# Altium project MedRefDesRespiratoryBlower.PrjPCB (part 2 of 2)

## Sheet Power Tree.SchDoc
size 431 x 279 mm; Date: Not shown in title block; ApprovedBy: Not shown in title block; CheckedBy: Not shown in title block; Author: Not shown in title block; CompanyName: Not shown in title block; Engineer: Not shown in title block; Organization: Not shown in title block; Address1: Not shown in title block; Address2: Not shown in title block; Address3: Not shown in title block; Address4: Not shown in title block; DocumentNumber: 5; Revision: Use project parameter SCH_Rev; SheetNumber: 5; SheetTotal: 6; PageSetup: Record=PageOptions¦CenterHorizontal=True¦CenterVertical=True¦PrintScale=1.00¦XCorrection=1.00¦YCorrection=1.00¦PrintKind=0¦BorderSize=5000000¦LeftOffset=0¦BottomOffset=0¦Orientation=2¦PaperLength=1000¦PaperWidth=1000¦Scale=100¦PaperSource=15¦PrintQuality=600¦MediaType=1¦DitherType=10¦PaperKind=Letter¦PrintScaleMode=1
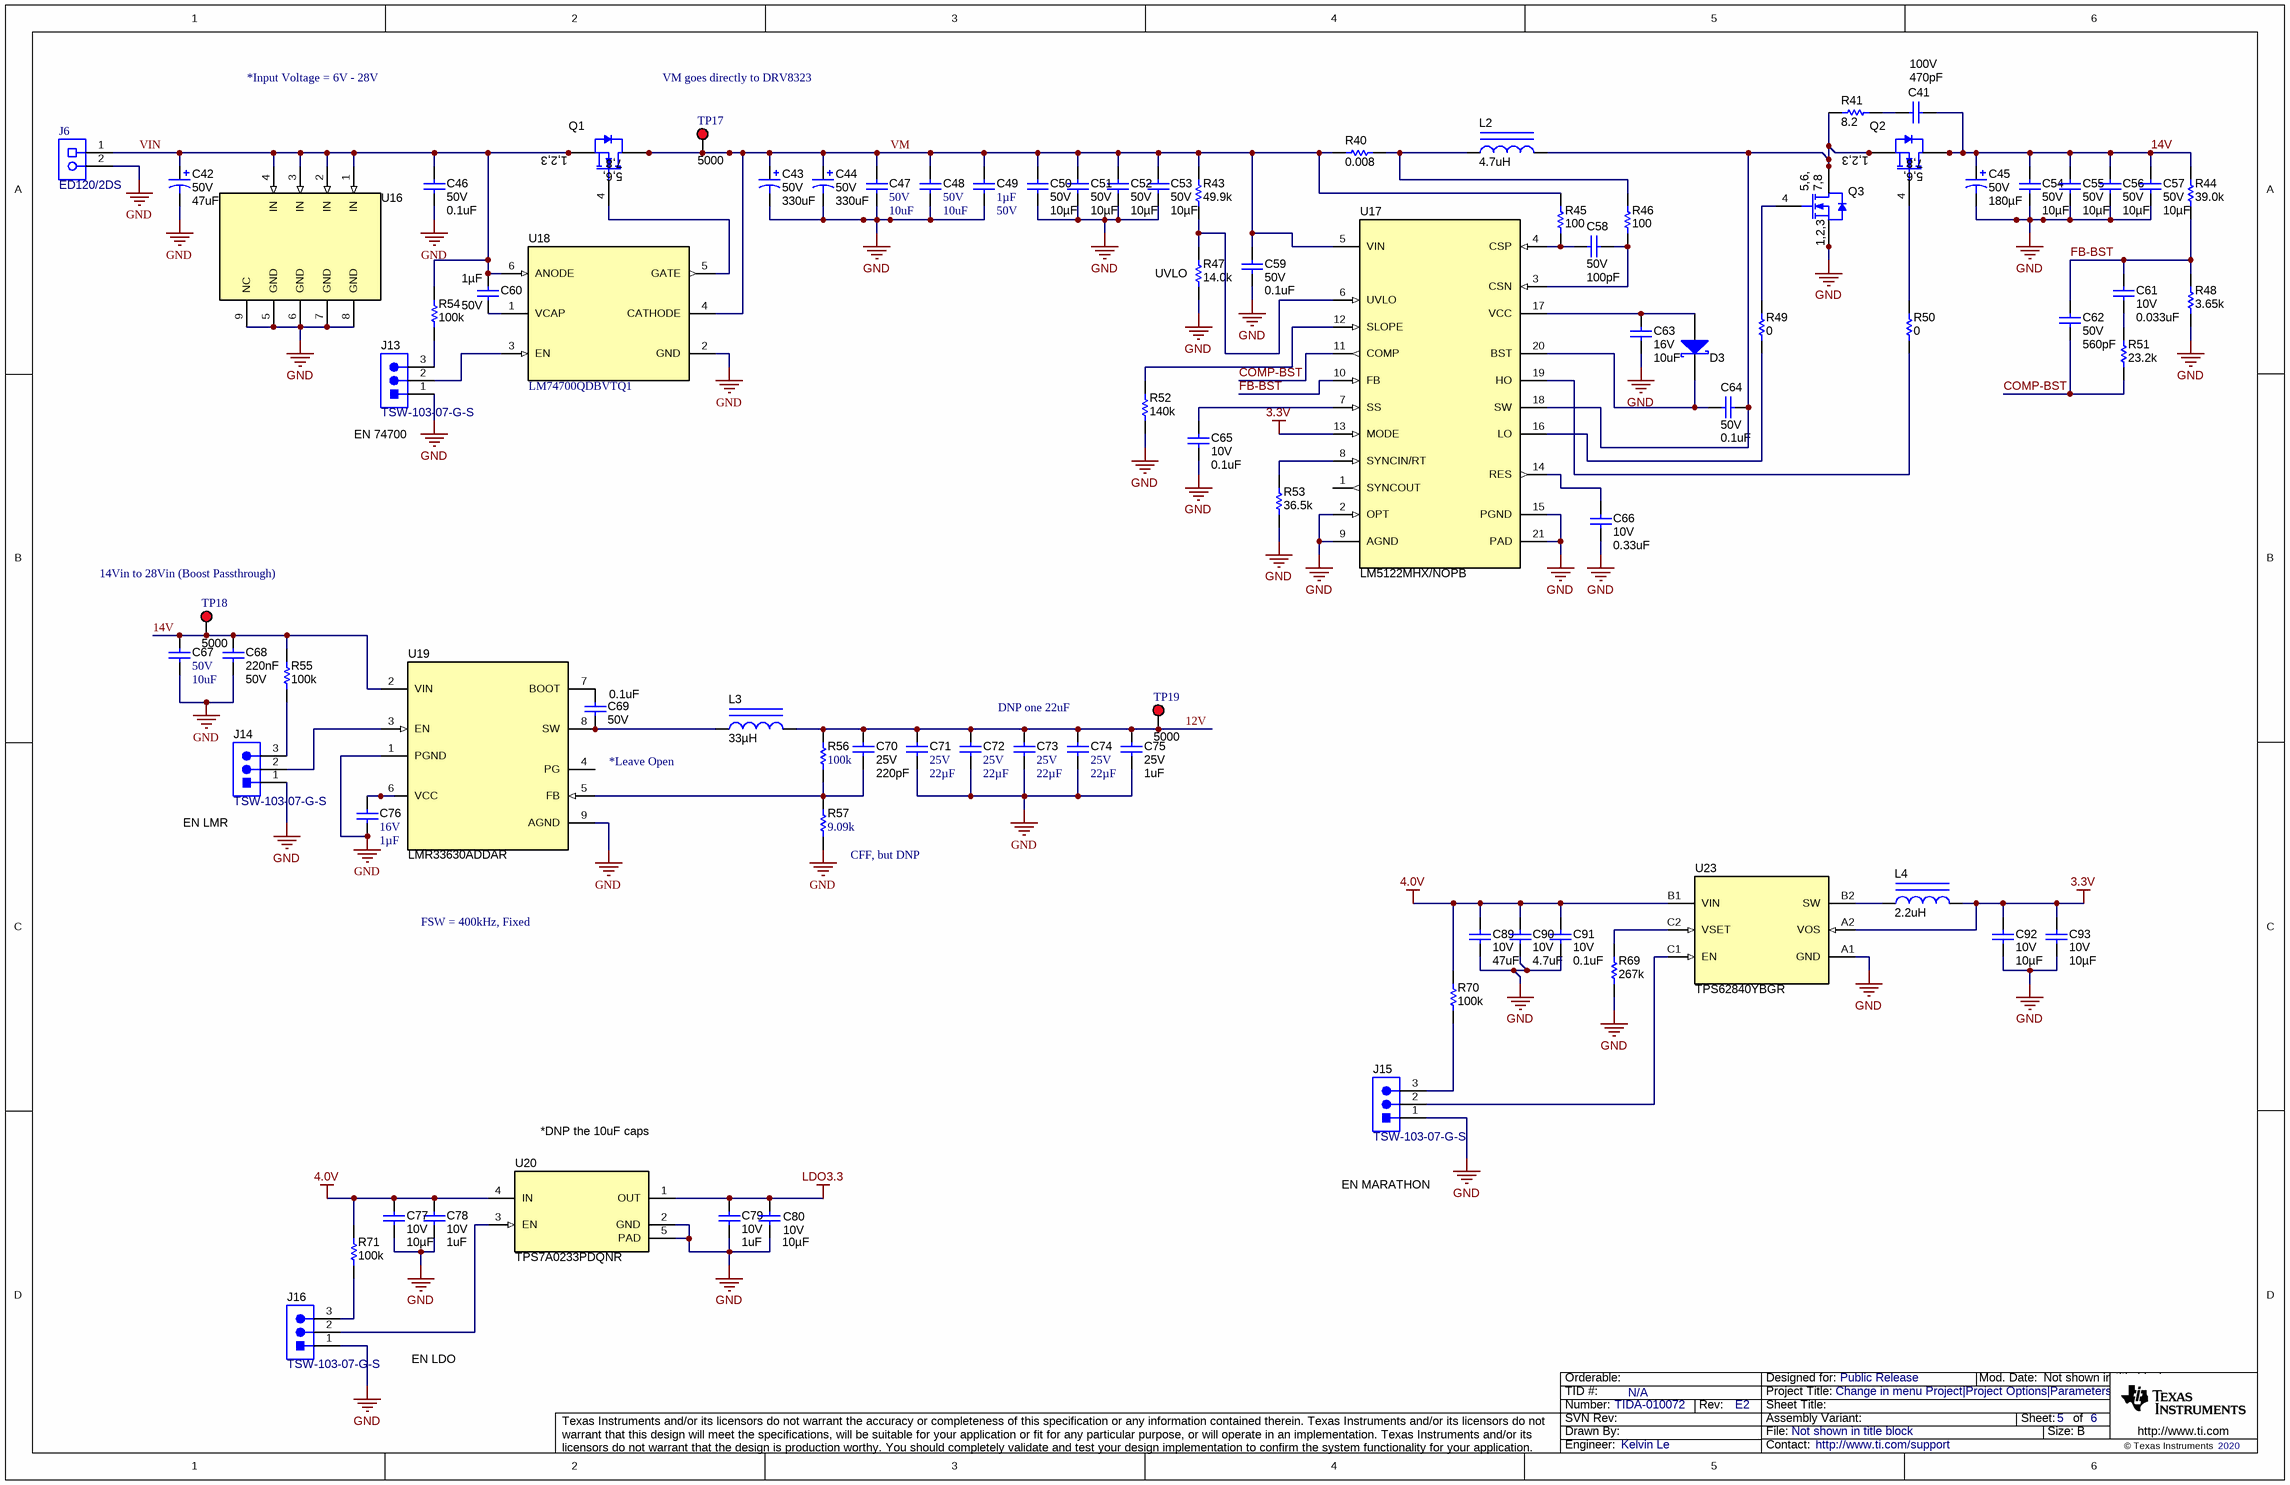
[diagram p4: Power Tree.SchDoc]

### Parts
C41  Cap_F: 470pF  VDC_V: 100V  [0603]  (hidden comment: GRM188R72A471KA01D)
C42  VDC_V: 50V  ValueDisplayed: 47uF  [CAPSMT_62_F80]  (hidden comment: EMZA500ADA470MF80G)
C43  VDC_V: 50V  ValueDisplayed: 330uF  [CAPSMT_62_KE0]  (hidden comment: EMVA500ATR331MKE0S)
C44  VDC_V: 50V  ValueDisplayed: 330uF  [CAPSMT_62_KE0]  (hidden comment: EMVA500ATR331MKE0S)
C45  VDC_V: 50V  ValueDisplayed: 180µF  [SM_RADIAL_F]  (hidden comment: EEE-FK1H181SP)
C46  VDC_V: 50V  ValueDisplayed: 0.1uF  [0402]  (hidden comment: C1005X7R1H104K050BB)
C47  VDC_V: 50V  ValueDisplayed: 10uF  [1206_180]  (hidden comment: CL31B106KBHNNNE)
C48  VDC_V: 50V  ValueDisplayed: 10uF  [1206_180]  (hidden comment: CL31B106KBHNNNE)
C49  Cap_F: 1µF  VDC_V: 50V  [0603]  (hidden comment: UMK107AB7105KA-T)
C50  VDC_V: 50V  ValueDisplayed: 10µF  [1206_190]  (hidden comment: UMK316BBJ106KL-T)
C51  VDC_V: 50V  ValueDisplayed: 10µF  [1206_190]  (hidden comment: UMK316BBJ106KL-T)
C52  VDC_V: 50V  ValueDisplayed: 10µF  [1206_190]  (hidden comment: UMK316BBJ106KL-T)
C53  VDC_V: 50V  ValueDisplayed: 10µF  [1206_190]  (hidden comment: UMK316BBJ106KL-T)
C54  VDC_V: 50V  ValueDisplayed: 10µF  [1206_190]  (hidden comment: UMK316BBJ106KL-T)
C55  VDC_V: 50V  ValueDisplayed: 10µF  [1206_190]  (hidden comment: UMK316BBJ106KL-T)
C56  VDC_V: 50V  ValueDisplayed: 10µF  [1206_190]  (hidden comment: UMK316BBJ106KL-T)
C57  VDC_V: 50V  ValueDisplayed: 10µF  [1206_190]  (hidden comment: UMK316BBJ106KL-T)
C58  VDC_V: 50V  ValueDisplayed: 100pF  [0402]  (hidden comment: 885012205055)
C59  VDC_V: 50V  ValueDisplayed: 0.1uF  [0402]  (hidden comment: GRM155R61H104ME14D)
C60  Cap_F: 1µF  VDC_V: 50V  [0603]  (hidden comment: UMK107AB7105KA-T)
C61  VDC_V: 10V  ValueDisplayed: 0.033uF  [0402]  (hidden comment: GRM155R61A333KA01D)
C62  VDC_V: 50V  ValueDisplayed: 560pF  [0402]  (hidden comment: GRM155R71H561KA01D)
C63  VDC_V: 16V  ValueDisplayed: 10uF  [0603]  (hidden comment: EMK107BBJ106MA-T)
C64  VDC_V: 50V  ValueDisplayed: 0.1uF  [0402]  (hidden comment: C1005X5R1H104K050BB)
C65  VDC_V: 10V  ValueDisplayed: 0.1uF  [0402]  (hidden comment: C1005X5R1A104K050BA)
C66  VDC_V: 10V  ValueDisplayed: 0.33uF  [0402]  (hidden comment: C1005X5R1A334K050BB)
C67  VDC_V: 50V  ValueDisplayed: 10uF  [1206_180]  (hidden comment: CL31B106KBHNNNE)
C68  Cap_F: 220nF  VDC_V: 50V  [0603]  (hidden comment: C1608X7R1H224K080AB)
C69  VDC_V: 50V  ValueDisplayed: 0.1uF  [0402]  (hidden comment: C1005X7R1H104K050BB)
C70  VDC_V: 25V  ValueDisplayed: 220pF  [0201]  (hidden comment: GRM033R71E221KA01D)
C71  VDC_V: 25V  ValueDisplayed: 22µF  [1210_270]  (hidden comment: GRT32ER61E226KE13L)
C72  VDC_V: 25V  ValueDisplayed: 22µF  [1210_270]  (hidden comment: GRT32ER61E226KE13L)
C73  VDC_V: 25V  ValueDisplayed: 22µF  [1210_270]  (hidden comment: GRT32ER61E226KE13L)
C74  VDC_V: 25V  ValueDisplayed: 22µF  [1210_270]  (hidden comment: GRT32ER61E226KE13L)
C75  VDC_V: 25V  ValueDisplayed: 1uF  [0402]  (hidden comment: GRM155R61E105KA12D)
C76  VDC_V: 16V  ValueDisplayed: 1µF  [0603]  (hidden comment: CC0603MRX5R7BB105)
C77  VDC_V: 10V  ValueDisplayed: 10µF  [0402_070]  (hidden comment: CC0402MRX5R6BB106)
C78  VDC_V: 10V  ValueDisplayed: 1uF  [0402]  (hidden comment: GRM155R61A105KE15D)
C79  VDC_V: 10V  ValueDisplayed: 1uF  [0402]  (hidden comment: GRM155R61A105KE15D)
C80  VDC_V: 10V  ValueDisplayed: 10µF  [0402_070]  (hidden comment: CC0402MRX5R6BB106)
C89  VDC_V: 10V  ValueDisplayed: 47uF  [0805_HV]  (hidden comment: C2012X5R1A476M125AC)
C90  VDC_V: 10V  ValueDisplayed: 4.7uF  [0402_065]  (hidden comment: C1005X5R1A475K050BC)
C91  VDC_V: 10V  ValueDisplayed: 0.1uF  [0402]  (hidden comment: 885012105010)
C92  VDC_V: 10V  ValueDisplayed: 10µF  [0402_070]  (hidden comment: CC0402MRX5R6BB106)
C93  VDC_V: 10V  ValueDisplayed: 10µF  [0402_070]  (hidden comment: CC0402MRX5R6BB106)
D3  MBR1H100SFT3G  [SOD-123FL]  (value not drawn)
J6  ED120/2DS  [On-Shore_ED120_2DS]
J13  TSW-103-07-G-S  [TSW-103-07-G-S]
J14  TSW-103-07-G-S  [TSW-103-07-G-S]
J15  TSW-103-07-G-S  [TSW-103-07-G-S]
J16  TSW-103-07-G-S  [TSW-103-07-G-S]
L2  ValueDisplayed: 4.7uH  [XAL6060]  (hidden comment: XAL6060-472MEB)
L3  ValueDisplayed: 33µH  [XAL6060]  (hidden comment: XAL6060-333MEB)
L4  ValueDisplayed: 2.2uH  [XFL3012]  (hidden comment: XFL3012-222MEB)
Q1  CSD18532Q5B  [DNK0008A]  (value not drawn)
Q2  CSD18543Q3A  [DNH0008A]  (value not drawn)
Q3  CSD18543Q3A  [DNH0008A]  (value not drawn)
R40  ValueDisplayed: 0.008  [2512]  (hidden comment: PMR100HZPFU8L00)
R41  ValueDisplayed: 8.2  [1210]  (hidden comment: RC1210JR-078R2L)
R43  ValueDisplayed: 49.9k  [0402]  (hidden comment: MCR01MZPF4992)
R44  ValueDisplayed: 39.0k  [0402]  (hidden comment: ERJ2RKF3902X)
R45  ValueDisplayed: 100  [0402]  (hidden comment: CRCW0402100RFKED)
R46  ValueDisplayed: 100  [0402]  (hidden comment: CRCW0402100RFKED)
R47  ValueDisplayed: 14.0k  [0402]  (hidden comment: RC0402FR-0714KL)
R48  ValueDisplayed: 3.65k  [0402]  (hidden comment: CRCW04023K65FKED)
R49  ValueDisplayed: 0  [0402]  (hidden comment: CRCW04020000Z0EDHP)
R50  ValueDisplayed: 0  [0402]  (hidden comment: CRCW04020000Z0EDHP)
R51  ValueDisplayed: 23.2k  [0402]  (hidden comment: CRCW040223K2FKED)
R52  ValueDisplayed: 140k  [0402]  (hidden comment: CRCW0402140KFKED)
R53  ValueDisplayed: 36.5k  [0402]  (hidden comment: CRCW040236K5FKED)
R54  ValueDisplayed: 100k  [0402]  (hidden comment: CRCW0402100KJNED)
R55  ValueDisplayed: 100k  [0402]  (hidden comment: CRCW0402100KJNED)
R56  ValueDisplayed: 100k  [0402]  (hidden comment: RMCF0402FT100K)
R57  ValueDisplayed: 9.09k  [0402]  (hidden comment: CRCW04029K09FKED)
R69  ValueDisplayed: 267k  [0402]  (hidden comment: CRCW0402267KFKED)
R70  ValueDisplayed: 100k  [0402]  (hidden comment: CRCW0402100KJNED)
R71  ValueDisplayed: 100k  [0402]  (hidden comment: CRCW0402100KJNED)
TP17  5000  [Keystone5000]
TP18  5000  [Keystone5000]
TP19  5000  [Keystone5000]
U16  TVS3301DRBR  [DRB0008A]  (value not drawn)
U17  LM5122MHX/NOPB  [PWP0020A_N]
U18  LM74700QDBVTQ1  [DBV0006A_N]
U19  LMR33630ADDAR  [DDA0008J]
U20  TPS7A0233PDQNR  [DQN0004A]
U23  TPS62840YBGR  [YBG0006AJAN]

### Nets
3.3V: C92.1 C93.1 L4.2 U17.13(MODE) U23.A2(VOS)
4.0V: C77.1 C78.1 C89.1 C90.1 C91.1 R70.2 R71.2 U20.4(IN) U23.B1(VIN)
GND: C42.2(-) C43.2(-) C44.2(-) C45.2(-) C46.2 C47.2 C48.2 C49.2 C50.2 C51.2 C52.2 C53.2 C54.2 C55.2 C56.2 C57.2 C59.2 C63.2 C65.2 C66.2 C67.2 C68.2 C71.2 C72.2 C73.2 C74.2 C75.2 C76.2 C77.2 C78.2 C79.2 C80.2 C89.2 C90.2 C91.2 C92.2 C93.2 J6.2 J13.1 J14.1 J15.1 J16.1 Q3.1(S) Q3.2(S) Q3.3(S) R47.1 R48.1 R52.1 R53.1 R57.1 R69.1 U16.5(GND) U16.6(GND) U16.7(GND) U16.8(GND) U16.9(NC) U17.2(OPT) U17.9(AGND) U17.15(PGND) U17.21(PAD) U18.2(GND) U19.1(PGND) U19.9(AGND) U20.2(GND) U20.5(PAD) U23.A1(GND)
LDO3.3: C79.1 C80.1 U20.1(OUT)
VM: C43.1(+) C44.1(+) C47.1 C48.1 C49.1 C50.1 C51.1 C52.1 C53.1 C59.1 Q1.5(D) Q1.6(D) Q1.7(D) Q1.8(D) Q1.9(D) R40.1 R43.2 R45.2 TP17.1 U17.5(VIN) U18.4(CATHODE)  [project net VDRAIN]
12V: C70.1 C71.1 C72.1 C73.1 C74.1 C75.1 L3.2 R56.2 TP19.1
14V: C41.1 C45.1(+) C54.1 C55.1 C56.1 C57.1 C67.1 C68.1 Q2.5(D) Q2.6(D) Q2.7(D) Q2.8(D) Q2.9(D) R44.2 R55.2 TP18.1 U19.2(VIN)
COMP-BST: C62.2 R51.1 U17.11(COMP)
FB-BST: C61.1 C62.1 R44.1 R48.2 U17.10(FB)
VIN: C42.1(+) C46.1 C60.1 J6.1 Q1.1(S) Q1.2(S) Q1.3(S) R54.2 U16.1(IN) U16.2(IN) U16.3(IN) U16.4(IN) U18.6(ANODE)
NetC41_2: C41.2 R41.2
NetC58_1: C58.1 R46.1 U17.3(CSN)
NetC58_2: C58.2 R45.1 U17.4(CSP)
NetC60_2: C60.2 U18.1(VCAP)
NetC61_2: C61.2 R51.2
NetC63_1: C63.1 D3.2(A) U17.17(VCC)
NetC64_1: C64.1 L2.2 Q2.1(S) Q2.2(S) Q2.3(S) Q3.5(D) Q3.6(D) Q3.7(D) Q3.8(D) Q3.9(D) R41.1 U17.18(SW)
NetC64_2: C64.2 D3.1(K) U17.20(BST)
NetC65_1: C65.1 U17.7(SS)
NetC66_1: C66.1 U17.14(RES)
NetC69_1: C69.1 U19.7(BOOT)
NetC69_2: C69.2 L3.1 U19.8(SW)
NetC70_2: C70.2 R56.1 R57.2 U19.5(FB)
NetC76_1: C76.1 U19.6(VCC)
NetJ13_2: J13.2 U18.3(EN)
NetJ13_3: J13.3 R54.1
NetJ14_2: J14.2 U19.3(EN)
NetJ14_3: J14.3 R55.1
NetJ15_2: J15.2 U23.C1(EN)
NetJ15_3: J15.3 R70.1
NetJ16_2: J16.2 U20.3(EN)
NetJ16_3: J16.3 R71.1
NetL2_1: L2.1 R40.2 R46.2
NetL4_1: L4.1 U23.B2(SW)
NetQ1_4: Q1.4(G) U18.5(GATE)
NetQ2_4: Q2.4(G) R50.2
NetQ3_4: Q3.4(G) R49.2
NetR43_1: R43.1 R47.2 U17.6(UVLO)
NetR49_1: R49.1 U17.16(LO)
NetR50_1: R50.1 U17.19(HO)
NetR52_2: R52.2 U17.12(SLOPE)
NetR53_2: R53.2 U17.8(SYNCIN/RT)
NetR69_2: R69.2 U23.C2(VSET)

Not connected (* = marked no-connect by the designer): U17 1(SYNCOUT); U19 4(PG)

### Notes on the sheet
- *Input Voltage = 6V - 28V
- VM goes directly to DRV8323
- (near R47) UVLO
- (near J13) EN 74700
- (near TP18) 14Vin to 28Vin (Boost Passthrough)
- *Leave Open
- DNP one 22uF
- (near J14) EN LMR
- (near R57) CFF, but DNP
- FSW = 400kHz, Fixed
- *DNP the 10uF caps
- EN MARATHON
- EN LDO

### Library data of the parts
C41 = CMP-0007482-3: CAP, CERM, 470 pF, 100 V, +/- 10%, X7R, 0603; Manufacturer: MuRata; TaMin_C: -55°C; Polarized: N; SizeAreaWB_mm2: 4.68; Value1: Unknown; U/M: EA; Value: 470pF; TaMax_C: 125°C; SizeZ_mm: 1; SizeX_mm: 1.6; SizeY_mm: 0.8; SizeArea_mm2: 1.28; AEC Category: Q200
C42 = CMP-0011388-2: CAP, AL, 47 uF, 50 V, +/- 20%, 0.68 ohm, SMD; Manufacturer: Chemi-Con; TaMin_C: -55°C; ESR_ohm: 0.68; Polarized: Y; SizeAreaWB_mm2: 73.96; U/M: EA; Value: 47uF; TaMax_C: 105°C; SizeZ_mm: 7.7; SizeX_mm: 6.6; Cap_Case: F80; SizeArea_mm2: 43.56; CompType: Capacitor; Cap_F: 47µF; IRMS_A: 195mA; AEC Category: Q200
C43 C44 = CMP-0011243-1: CAP, AL, 330 uF, 50 V, +/- 20%, SMD; Manufacturer: Chemi-Con; TaMin_C: -40°C; Polarized: Y; SizeAreaWB_mm2: 225; Value1: Unknown; U/M: EA; Value: 330uF; TaMax_C: 85°C; SizeZ_mm: 13.5; SizeX_mm: 13; Cap_Case: KE0; SizeArea_mm2: 169; CompType: Capacitor; Cap_F: 330µF; IRMS_A: 600mA; AEC Category: Q200
C45 = CMP-0078149-1: CAP, AL, 180 µF, 50 V, +/- 20%, 0.34 ohm, AEC-Q200 Grade 2, SMD; Manufacturer: Panasonic; IRMS_A: 350mA; SizeAreaWB_mm2: 123.6; SizeArea_mm2: 83; AEC Qualified: Y; AEC Category: Q200; Value: 180uF; TaMax_C: 105°C; SizeZ_mm: 10.2; AEC Grade: 2; TaMin_C: -55°C; SizeY_mm: 8.3; U/M: EA; CompType: Capacitor; SizeX_mm: 10; ESR_ohm: 0.34; Cap_Case: 8X10.2mm
C46 C69 = CMP-0006297-2: CAP, CERM, 0.1 uF, 50 V, +/- 10%, X7R, 0402; Manufacturer: TDK; TaMin_C: -55°C; ESR_ohm: 0.039064; Polarized: N; SizeAreaWB_mm2: 3; Value1: 0.039064 ohm; U/M: EA; Value: 0.1uF; TaMax_C: 125°C; SizeZ_mm: 0.6; SizeX_mm: 1; SizeY_mm: 0.5; Cap_F: 100nF; IRMS_A: 814.669mA; AEC Category: Q200
C47 C48 C67 = CMP-0008802-2: CAP, CERM, 10 uF, 50 V, +/- 10%, X7R, 1206; Manufacturer: Samsung; TaMin_C: -55°C; Polarized: N; SizeAreaWB_mm2: 10.92; Value1: Unknown; U/M: EA; Value: 10uF; TaMax_C: 125°C; SizeZ_mm: 1.8; SizeX_mm: 3.2; SizeY_mm: 1.6; Cap_Case: 1206; SizeArea_mm2: 5.12; Cap_F: 10µF; AEC Category: Q200
C49 C60 = CMP-0007508-5: CAP, CERM, 1 uF, 50 V, +/- 10%, X7R, 0603; Manufacturer: Taiyo Yuden; TaMin_C: -55°C; Polarized: N; SizeAreaWB_mm2: 4.68; Value1: Unknown; U/M: EA; Value: 1uF; TaMax_C: 125°C; SizeZ_mm: 1; SizeX_mm: 1.6; SizeY_mm: 0.8; SizeArea_mm2: 1.28; AEC Category: Q200
C50-C57 = CMP-0086153-1: CAP, CERM, 10 µF, 50 V,+/- 10%, X5R, 1206; Manufacturer: Taiyo Yuden; Polarized: N; SizeX_mm: 3.2; TaMax_C: 85°C; SizeY_mm: 1.6; AEC Category: Q200; SizeArea_mm2: 5.12; Cap_Case: 1206; SizeAreaWB_mm2: 10.92; TaMin_C: -55°C; SizeZ_mm: 1.9; U/M: EA; Value: 10uF
C58 = CMP-0006230-2: CAP, CERM, 100 pF, 50 V, +/- 10%, X7R, 0402; Manufacturer: Wurth Elektronik; TaMin_C: -55°C; Polarized: N; SizeAreaWB_mm2: 3; Value1: Unknown; U/M: EA; Value: 100pF; TaMax_C: 125°C; SizeZ_mm: 0.6; SizeX_mm: 1; SizeY_mm: 0.5; AEC Category: Q200
C59 = CMP-0006614-2: CAP, CERM, 0.1 uF, 50 V, +/- 20%, X5R, 0402; Manufacturer: MuRata; TaMin_C: -55°C; Polarized: N; SizeAreaWB_mm2: 3; Value1: Unknown; U/M: EA; Value: 0.1uF; TaMax_C: 85°C; SizeZ_mm: 0.6; SizeX_mm: 1; SizeY_mm: 0.5; Cap_F: 100nF; AEC Category: Q200
C61 = CMP-0006574-2: CAP, CERM, 0.033 uF, 10 V, +/- 10%, X5R, 0402; Manufacturer: MuRata; TaMin_C: -55°C; Polarized: N; SizeAreaWB_mm2: 3; Value1: Unknown; U/M: EA; TaMax_C: 85°C; SizeZ_mm: 0.6; SizeX_mm: 1; SizeY_mm: 0.5; Cap_F: 33nF; AEC Category: Q200
C62 = CMP-0006693-2: CAP, CERM, 560 pF, 50 V, +/- 10%, X7R, 0402; Manufacturer: MuRata; TaMin_C: -55°C; Polarized: N; SizeAreaWB_mm2: 3; Value1: Unknown; U/M: EA; Value: 560pF; TaMax_C: 125°C; SizeZ_mm: 0.6; SizeX_mm: 1; SizeY_mm: 0.5; AEC Category: Q200
C63 = CMP-0007122-5: CAP, CERM, 10 uF, 16 V, +/- 20%, X5R, 0603; Manufacturer: Taiyo Yuden; TaMin_C: -55°C; Polarized: N; SizeAreaWB_mm2: 4.68; Value1: Unknown; U/M: EA; Value: 10uF; TaMax_C: 85°C; SizeZ_mm: 1; SizeX_mm: 1.6; SizeY_mm: 0.8; SizeArea_mm2: 1.28; Cap_F: 10µF; AEC Category: Q200
C64 = CMP-0006279-2: CAP, CERM, 0.1 uF, 50 V, +/- 10%, X5R, 0402; Manufacturer: TDK; TaMin_C: -55°C; ESR_ohm: 0.039064; Polarized: N; SizeAreaWB_mm2: 3; Value1: 0.039064 ohm; U/M: EA; Value: 0.1uF; TaMax_C: 85°C; SizeZ_mm: 0.6; SizeX_mm: 1; SizeY_mm: 0.5; Cap_F: 100nF; IRMS_A: 814.669mA; AEC Category: Q200
C65 = CMP-0006259-2: CAP, CERM, 0.1 uF, 10 V, +/- 10%, X5R, 0402; Manufacturer: TDK; TaMin_C: -55°C; Polarized: N; SizeAreaWB_mm2: 3; Value1: Unknown; U/M: EA; Value: 0.1uF; TaMax_C: 85°C; SizeZ_mm: 0.6; SizeX_mm: 1; SizeY_mm: 0.5; Cap_F: 100nF; AEC Category: Q200
C66 = CMP-0006264-2: CAP, CERM, 0.33 uF, 10 V, +/- 10%, X5R, 0402; Manufacturer: TDK; TaMin_C: -55°C; Polarized: N; SizeAreaWB_mm2: 3; Value1: Unknown; U/M: EA; Value: 0.33uF; TaMax_C: 85°C; SizeZ_mm: 0.6; SizeX_mm: 1; SizeY_mm: 0.5; Cap_F: 330nF; AEC Category: Q200
C68 = CMP-0007047-4: CAP, CERM, 0.22 uF, 50 V, +/- 10%, X7R, 0603; Manufacturer: TDK; TaMin_C: -55°C; ESR_ohm: 0.021699; Polarized: N; SizeAreaWB_mm2: 4.68; Value1: 0.021699 ohm; U/M: EA; Value: 0.22uF; TaMax_C: 125°C; SizeZ_mm: 1; SizeX_mm: 1.6; SizeY_mm: 0.8; SizeArea_mm2: 1.28; IRMS_A: 1.12496A; AEC Category: Q200
C70 = CMP-0009770-1: CAP, CERM, 220 pF, 25 V, +/- 10%, X7R, 0201; Manufacturer: MuRata; TaMin_C: -55°C; Polarized: N; SizeAreaWB_mm2: 2.08; Value1: Unknown; U/M: EA; Value: 220pF; TaMax_C: 125°C; SizeZ_mm: 0.26; SizeX_mm: 0.6; SizeY_mm: 0.3; SizeArea_mm2: 0.18; AEC Category: Q200
C71-C74 = CMP-0084059-1: CAP, CERM, 22 µF, 25 V,+/- 10%, X5R, AEC-Q200 Grade 3, 1210; Manufacturer: MuRata; SizeAreaWB_mm2: 14.7; SizeArea_mm2: 8; AEC Qualified: Y; AEC Category: Q200; Value: 22uF; TaMax_C: 85°C; SizeZ_mm: 2.7; AEC Grade: 3; Polarized: N; TaMin_C: -55°C; SizeY_mm: 2.5; U/M: EA; SizeX_mm: 3.2; Cap_Case: 1210
C75 = CMP-0006608-2: CAP, CERM, 1 uF, 25 V, +/- 10%, X5R, 0402; Manufacturer: MuRata; TaMin_C: -55°C; Polarized: N; SizeAreaWB_mm2: 3; Value1: Unknown; U/M: EA; Value: 1uF; TaMax_C: 85°C; SizeZ_mm: 0.6; SizeX_mm: 1; SizeY_mm: 0.5; Cap_F: 1µF; AEC Category: Q200
C76 = CMP-0081458-1: CAP, CERM, 1 µF, 16 V,+/- 20%, X5R, 0603; Manufacturer: Yageo America; TaMin_C: -55°C; Polarized: N; SizeAreaWB_mm2: 4.68; U/M: EA; Value: 1uF; TaMax_C: 85°C; SizeZ_mm: 1; SizeX_mm: 1.6; SizeY_mm: 0.8; SizeArea_mm2: 1.28; AEC Category: Q200
C77 C80 C92 C93 = CMP-0084008-1: CAP, CERM, 10 µF, 10 V,+/- 20%, X5R, 0402; Manufacturer: Yageo; TaMin_C: -55°C; ESR_ohm: 1m; Polarized: N; SizeAreaWB_mm2: 3; Value1: 0.001 ohm; U/M: EA; Value: 10uF; TaMax_C: 85°C; SizeZ_mm: 0.7; SizeX_mm: 1; SizeY_mm: 0.5; Cap_Case: 0402; AEC Category: Q200
C78 C79 = CMP-0006563-2: CAP, CERM, 1 uF, 10 V, +/- 10%, X5R, 0402; Manufacturer: MuRata; TaMin_C: -55°C; Polarized: N; SizeAreaWB_mm2: 3; Value1: Unknown; U/M: EA; Value: 1uF; TaMax_C: 85°C; SizeZ_mm: 0.6; SizeX_mm: 1; SizeY_mm: 0.5; Cap_F: 1µF; AEC Category: Q200
C89 = CMP-0007825-2: CAP, CERM, 47 uF, 10 V, +/- 20%, X5R, 0805; Manufacturer: TDK; TaMin_C: -55°C; ESR_ohm: 2.94m; Polarized: N; SizeAreaWB_mm2: 6.75; Value1: 0.00294 ohm; U/M: EA; Value: 47uF; TaMax_C: 85°C; SizeZ_mm: 1.45; SizeX_mm: 2; SizeY_mm: 1.25; Cap_Case: 0805; SizeArea_mm2: 2.5; Cap_F: 47µF; IRMS_A: 3.80451A; AEC Category: Q200
C90 = CMP-0006268-2: CAP, CERM, 4.7 uF, 10 V, +/- 10%, X5R, 0402; Manufacturer: TDK; TaMin_C: -55°C; ESR_ohm: 3.417m; Polarized: N; SizeAreaWB_mm2: 3; Value1: 0.003417 ohm; U/M: EA; Value: 4.7uF; TaMax_C: 85°C; SizeZ_mm: 0.65; SizeX_mm: 1; SizeY_mm: 0.5; Cap_F: 4.7µF; IRMS_A: 2.7063A; AEC Category: Q200
C91 = CMP-0006221-2: CAP, CERM, 0.1 uF, 10 V, +/- 20%, X5R, 0402; Manufacturer: Wurth Elektronik; TaMin_C: -55°C; Polarized: N; SizeAreaWB_mm2: 3; Value1: Unknown; U/M: EA; Value: 0.1uF; TaMax_C: 85°C; SizeZ_mm: 0.6; SizeX_mm: 1; SizeY_mm: 0.5; Cap_F: 100nF; AEC Category: Q200
D3 = CMP-0028625-2: Diode, Schottky, 100 V, 1 A, SOD-123FL; Manufacturer: ON Semiconductor; Io_A: 1A; Green_Lifecycle: Active; SizeAreaWB_mm2: 12.19; Vr_V: 100V; Green_REACh: Passed; TJmax_C: 175°C; Value: 100V; SizeZ_mm: 0.98; SizeX_mm: 3.6; SizeY_mm: 1.65; Vf_V: 760mV; Value2: 0.76V; SizeArea_mm2: 5.94; AEC Category: Q101; RJC_CperW: 85
J6 = CMP-0074910-1: Terminal Block, 5.08 mm, 2x1, Brass, TH; Manufacturer: On-Shore Technology; Cert_VDE: Y; CNHeader: False; Current_A: 15A; Green_Lifecycle: Not Set; Shrouded: N; Gender: Female; Green_REACh: Incomplete; Voltage_V: 300V; Row_Count: 1; Pitch_mm: 5.08; CT: True
J13-J16 = CMP-0075407-2: Header, 100mil, 3x1, Gold, TH; Manufacturer: Samtec; Pitch_mm: 2.54; Cert_VDE: N; Gender: Male; Cert_CSA: Y; Voltage_V: 550V; Green_REACh: Passed; Current_A: 6.3A; Green_Lifecycle: Active; Row_Count: 1
L2 = CMP-0061020-2: Inductor, Shielded, Composite, 4.7 µH, 10.5 A, 0.0144 ohm, AEC-Q200 Grade 1, SMD; Manufacturer: Coilcraft; SizeZ_mm: 6.1; Ind_H: 4.7µH; AEC Qualified: Y; Imax_A: 10.5A; Value: 4.7uH; SizeY_mm: 6.56; AEC Category: Q200; SizeAreaWB_mm2: 71.5616; Green_REACh: Incomplete; DCR_ohm: 0.0144; Isat: 10.5A @ 30% inductance drop; Green_Lifecycle: Not Set; SizeX_mm: 6.36; SizeArea_mm2: 41.7216; AEC Grade: 1; Irms: 12.3A @ 40C rise
L3 = CMP-0085398-2: Inductor, Shielded, Composite, 33 µH, 3.6 A, 0.105 ohm, AEC-Q200 Grade 1, SMD; Manufacturer: Coilcraft; Isat: 3.7A @ 30% inductance drop; AEC Qualified: Y; Green_Lifecycle: Not Set; SizeX_mm: 6.36; SizeAreaWB_mm2: 71.5616; AEC Category: Q200; Value: 33uH; SizeY_mm: 6.56; AEC Grade: 1; SizeZ_mm: 6.1; Green_REACh: Incomplete; DCR_ohm: 0.105; Value2: 3.6A; Irms: 3.6A @ 40C rise; SizeArea_mm2: 41.7216
L4 = CMP-0061137-1: Inductor, Shielded, Composite, 2.2 uH, 1.6 A, 0.08 ohm, SMD; Manufacturer: Coilcraft; Isat: 1.6A @ 30% inductance drop; Irms: 1.9A @ 40C rise; Green_Lifecycle: Not Set; SizeAreaWB_mm2: 16; DCR_ohm: 0.08; Green_REACh: Incomplete; Value: 2.2uH; Imax_A: 1.6A; SizeZ_mm: 1.2; SizeX_mm: 3; SizeArea_mm2: 9; Ind_H: 2.2µH; AEC Category: Q200
Q1 = CMP-0000813-2: MOSFET, N-CH, 60 V, 172 A, DNK0008A (VSON-CLIP-8); Alternate Manufacturer: None; Manufacturer: Texas Instruments; SizeZ_mm: 1; ChType: N; Value2: 27 nC; Value1: 3; VdsMax_V: 60V; SizeX_mm: 6; SizeY_mm: 5; Vgs_V: 1.6V; Value: 60V; Rdson45_ohm: 3.3; SizeArea_mm2: 30; AEC Category: Q101; IdsMax_A: 172A; SizeAreaWB_mm2: 56; U/M: EA; QgTyp_nC: 27
Q2 Q3 = CMP-0000826-2: MOSFET, N-CH, 60 V, 35 A, DNH0008A (VSONP-8); Alternate Manufacturer: None; Manufacturer: Texas Instruments; SizeZ_mm: 0.9; ChType: N; Value2: 11.1 nC; Value1: 0.01; VdsMax_V: 60V; SizeX_mm: 3.3; SizeAreaWB_mm2: 18.49; Vgs_V: 20V; QgTyp_nC: 11.1; Value: 60V; Rdson45_ohm: 0.012; SizeArea_mm2: 10.89; AEC Category: Q101; IdsMax_A: 35A; ChMode: Enhancement
R40 = CMP-0015840-2: RES, 0.008, 1%, 2 W, 2512; Manufacturer: Rohm; Power_W: 2W; TempCo: 100 ppm/C; Value_Code: 8L000; U/M: EA; Value: 0.008; EIA_Code: E96; Res_ohm: 8m; SizeX_mm: 6.3; SizeY_mm: 3.2; SizeZ_mm: 0.71; SizeArea_mm2: 20.16; AEC Category: Q200
R41 = CMP-0083607-1: RES, 8.2, 5%, 0.5 W, 1210; Manufacturer: Yageo; Power_W: 500mW; TempCo: 200 ppm/C; SizeAreaWB_mm2: 14.7; Value_Code: 8R20; Value: 8.2; EIA_Code: E24; SizeX_mm: 3.2; SizeY_mm: 2.5; SizeZ_mm: 1.35; Value2: 0.5W; SizeArea_mm2: 8; AEC Qualified: N; VDC_V: 200V; AEC Category: Q200
R43 = CMP-0026718-1: RES, 49.9 k, 1%, 0.063 W, 0402; Manufacturer: Rohm; Power_W: 63mW; TempCo: 100 ppm/C; Value_Code: 49k9; U/M: EA; Value: 49.9k; EIA_Code: E96; SizeX_mm: 1; SizeY_mm: 0.5; SizeZ_mm: 0.6; Value2: 0.063W; AEC Qualified: N; VDC_V: 50V; AEC Category: Q200
R44 = CMP-0081725-1: RES, 39.0 k, 1%, 0.1 W, AEC-Q200 Grade 0, 0402; Manufacturer: Panasonic; Power_W: 100mW; TempCo: 100 ppm/C; SizeAreaWB_mm2: 3; Value_Code: 39k0; Value: 39.0k; Res_ohm: 39k; SizeX_mm: 1; SizeY_mm: 0.5; SizeZ_mm: 0.6; Value2: 0.1W; AEC Qualified: Y; AEC Grade: 0; AEC Category: Q200
R45 R46 = CMP-0025951-3: RES, 100, 1%, 0.063 W, AEC-Q200 Grade 0, 0402; Manufacturer: Vishay-Dale; Power_W: 63mW; TempCo: 100 ppm/C; Value_Code: 100R; Value: 100; EIA_Code: E96; SizeX_mm: 1; SizeY_mm: 0.5; SizeZ_mm: 0.6; Value2: 0.063W; AEC Qualified: Y; VDC_V: 50V; AEC Category: Q200; AEC Grade: 0
R47 = CMP-0860046-1: RES, 14.0 k, 1%, 0.0625 W, 0402; Manufacturer: Yageo; Power_W: 62.5mW; SizeX_mm: 1; TempCo: 100 ppm/C; AEC Qualified: N; SizeArea_mm2: 0.5; AEC Category: Q200; SizeAreaWB_mm2: 3; SizeZ_mm: 0.6; Value: 14.0k; Res_ohm: 14k; VDC_V: 50V; Value_Code: 14k0; EIA_Code: E96
R48 = CMP-0026337-2: RES, 3.65 k, 1%, 0.063 W, AEC-Q200 Grade 0, 0402; Manufacturer: Vishay-Dale; Power_W: 63mW; TempCo: 100 ppm/C; Value_Code: 3k65; Value: 3.65k; EIA_Code: E96; SizeX_mm: 1; SizeY_mm: 0.5; SizeZ_mm: 0.6; Value2: 0.063W; AEC Qualified: Y; VDC_V: 50V; AEC Category: Q200; AEC Grade: 0
R49 R50 = CMP-0081856-1: RES, 0, 0%, 0.2 W, AEC-Q200 Grade 0, 0402; Manufacturer: Vishay-Dale; SizeAreaWB_mm2: 3; SizeArea_mm2: 0.5; AEC Qualified: Y; AEC Category: Q200; Value: 0; SizeZ_mm: 0.6; Power_W: 200mW; VDC_V: 50V; Value2: 0.2W; SizeX_mm: 1
R51 = CMP-0026186-2: RES, 23.2 k, 1%, 0.063 W, AEC-Q200 Grade 0, 0402; Manufacturer: Vishay-Dale; Power_W: 63mW; TempCo: 100 ppm/C; Value_Code: 23k2; Value: 23.2k; EIA_Code: E96; SizeX_mm: 1; SizeY_mm: 0.5; SizeZ_mm: 0.6; Value2: 0.063W; AEC Qualified: Y; VDC_V: 50V; AEC Category: Q200; AEC Grade: 0
R52 = CMP-0026009-3: RES, 140 k, 1%, 0.063 W, AEC-Q200 Grade 0, 0402; Manufacturer: Vishay-Dale; Power_W: 63mW; TempCo: 100 ppm/C; Value: 140k; EIA_Code: E96; SizeX_mm: 1; SizeY_mm: 0.5; SizeZ_mm: 0.6; Value2: 0.063W; AEC Qualified: Y; VDC_V: 50V; AEC Category: Q200; AEC Grade: 0
R53 = CMP-0026315-2: RES, 36.5 k, 1%, 0.063 W, AEC-Q200 Grade 0, 0402; Manufacturer: Vishay-Dale; Power_W: 63mW; TempCo: 100 ppm/C; Value_Code: 36k5; Value: 36.5k; EIA_Code: E96; SizeX_mm: 1; SizeY_mm: 0.5; SizeZ_mm: 0.6; Value2: 0.063W; AEC Qualified: Y; VDC_V: 50V; AEC Category: Q200; AEC Grade: 0
R54 R55 R70 R71 = CMP-0026823-3: RES, 100 k, 5%, 0.063 W, AEC-Q200 Grade 0, 0402; Manufacturer: Vishay-Dale; Power_W: 63mW; TempCo: 200 ppm/C; Value: 100k; EIA_Code: E24; SizeX_mm: 1; SizeY_mm: 0.5; SizeZ_mm: 0.6; Value2: 0.063W; AEC Qualified: Y; VDC_V: 50V; AEC Category: Q200; AEC Grade: 0
R56 = CMP-0026753-1: RES, 100 k, 1%, 0.063 W, AEC-Q200 Grade 0, 0402; Manufacturer: Stackpole Electronics Inc; Power_W: 63mW; TempCo: 100 ppm/C; U/M: EA; Value: 100k; EIA_Code: E96; SizeX_mm: 1; SizeY_mm: 0.5; SizeZ_mm: 0.6; Value2: 0.063W; AEC Qualified: Y; VDC_V: 50V; AEC Grade: 0; AEC Category: Q200
R57 = CMP-0026619-3: RES, 9.09 k, 1%, 0.063 W, AEC-Q200 Grade 0, 0402; Manufacturer: Vishay-Dale; VDC_V: 50V; Value2: 0.063W; Power_W: 63mW; AEC Qualified: Y; SizeZ_mm: 0.6; TempCo: 100 ppm/C; SizeArea_mm2: 0.5; SizeX_mm: 1; Value: 9.09k; Value_Code: 9k09; AEC Category: Q200; AEC Grade: 0; EIA_Code: E96
R69 = CMP-0026205-1: RES, 267 k, 1%, 0.063 W, 0402; Manufacturer: Vishay-Dale; Power_W: 63mW; TempCo: 100 ppm/C; U/M: EA; Value: 267k; EIA_Code: E96; SizeX_mm: 1; SizeY_mm: 0.5; SizeZ_mm: 0.6; Value2: 0.063W; VDC_V: 50V; AEC Category: Q200
TP17-TP19 = CMP-0055137-1: Test Point, Miniature, Red, TH; Manufacturer: Keystone; CNHeader: FALSE; Green_Lifecycle: Active; Green_REACh: Passed; ContactFinish: Silver; CT: TRUE
U16 = CMP-0081715-3: 33 V Bidirectional Flat-Clamp Surge Protection Device, DRB0008A (VSON-8); Alternate PartNumber: TVS3301DRBT; Alternate Manufacturer: Texas Instruments; SizeZ_mm: 1.0; SizeX_mm: 3.0; AEC Category: Q200; SizeAreaWB_mm2: 16.0; CompType: IC; Rating: Catalog; SizeArea_mm2: 9.0; AEC Qualified: N
U17 = CMP-0066110-3: 3-65V Wide Vin, Current Mode Synchronous Boost Controller with Multiphase Capability, PWP0020A (HTSSOP-20); Alternate PartNumber: LM5122MHE/NOPB; Manufacturer: Texas Instruments; SizeZ_mm: 1.2; SizeX_mm: 6.4; SizeY_mm: 6.5; SizeArea_mm2: 41.6; CompType: IC; SizeAreaWB_mm2: 71.4; AEC Category: Q200; AEC Qualified: N; Rating: Catalog
U18 = CMP-0079180-1: Low Iq Always ON Smart Diode Controller, DBV0006A (SOT-23-6); Alternate PartNumber: LM74700QDBVRQ1; Alternate Manufacturer: Texas Instruments; SizeAreaWB_mm2: 14.82; SizeZ_mm: 1.45; SizeX_mm: 2.8; SizeY_mm: 2.9; SizeArea_mm2: 8.12; CompType: IC; AEC Qualified: Y; AEC Category: Q200
U19 = CMP-0013272-2: SIMPLE SWITCHER 3.8V to 36V 3A/2A Synchronous Step-Down Voltage Regulator, DDA0008J (SOIC-8); Alternate Manufacturer: Texas Instruments; SizeAreaWB_mm2: 55.0511; U/M: EA; SizeZ_mm: 1.7; SizeX_mm: 5.99; SizeY_mm: 4.89; SizeArea_mm2: 29.2911; CompType: IC
U20 = CMP-0081013-2: 1-uA IQ, 200-mA, Ultralow IQ Low-Dropout Regulator, DQN0004A (X2SON-4); Alternate Manufacturer: Texas Instruments; SizeAreaWB_mm2: 4; SizeZ_mm: 0.4; SizeX_mm: 1; CompType: IC; AEC Qualified: N; AEC Category: Q200
U23 = CMP-0081436-2: Ultra low IQ Step Down Converter, YBG0006AJAN (DSBGA-6); Manufacturer: Texas Instruments; CompType: IC; SizeX_mm: 0.97; AEC Category: Q200; AEC Qualified: N; SizeArea_mm2: 1.4259; SizeY_mm: 1.47; SizeZ_mm: 0.5; SizeAreaWB_mm2: 4.8659

## Sheet Valve Drivers and Fault Indicators.SchDoc
size 431 x 279 mm; Date: Not shown in title block; ApprovedBy: Not shown in title block; CheckedBy: Not shown in title block; Author: Not shown in title block; CompanyName: Not shown in title block; Engineer: Not shown in title block; Organization: Not shown in title block; Address1: Not shown in title block; Address2: Not shown in title block; Address3: Not shown in title block; Address4: Not shown in title block; DocumentNumber: 6; Revision: Use project parameter SCH_Rev; SheetNumber: 6; SheetTotal: 6; PageSetup: Record=PageOptions¦CenterHorizontal=True¦CenterVertical=True¦PrintScale=1.00¦XCorrection=1.00¦YCorrection=1.00¦PrintKind=0¦BorderSize=5000000¦LeftOffset=0¦BottomOffset=0¦Orientation=2¦PaperLength=1000¦PaperWidth=1000¦Scale=100¦PaperSource=15¦PrintQuality=600¦MediaType=1¦DitherType=10¦PaperKind=Letter¦PrintScaleMode=1
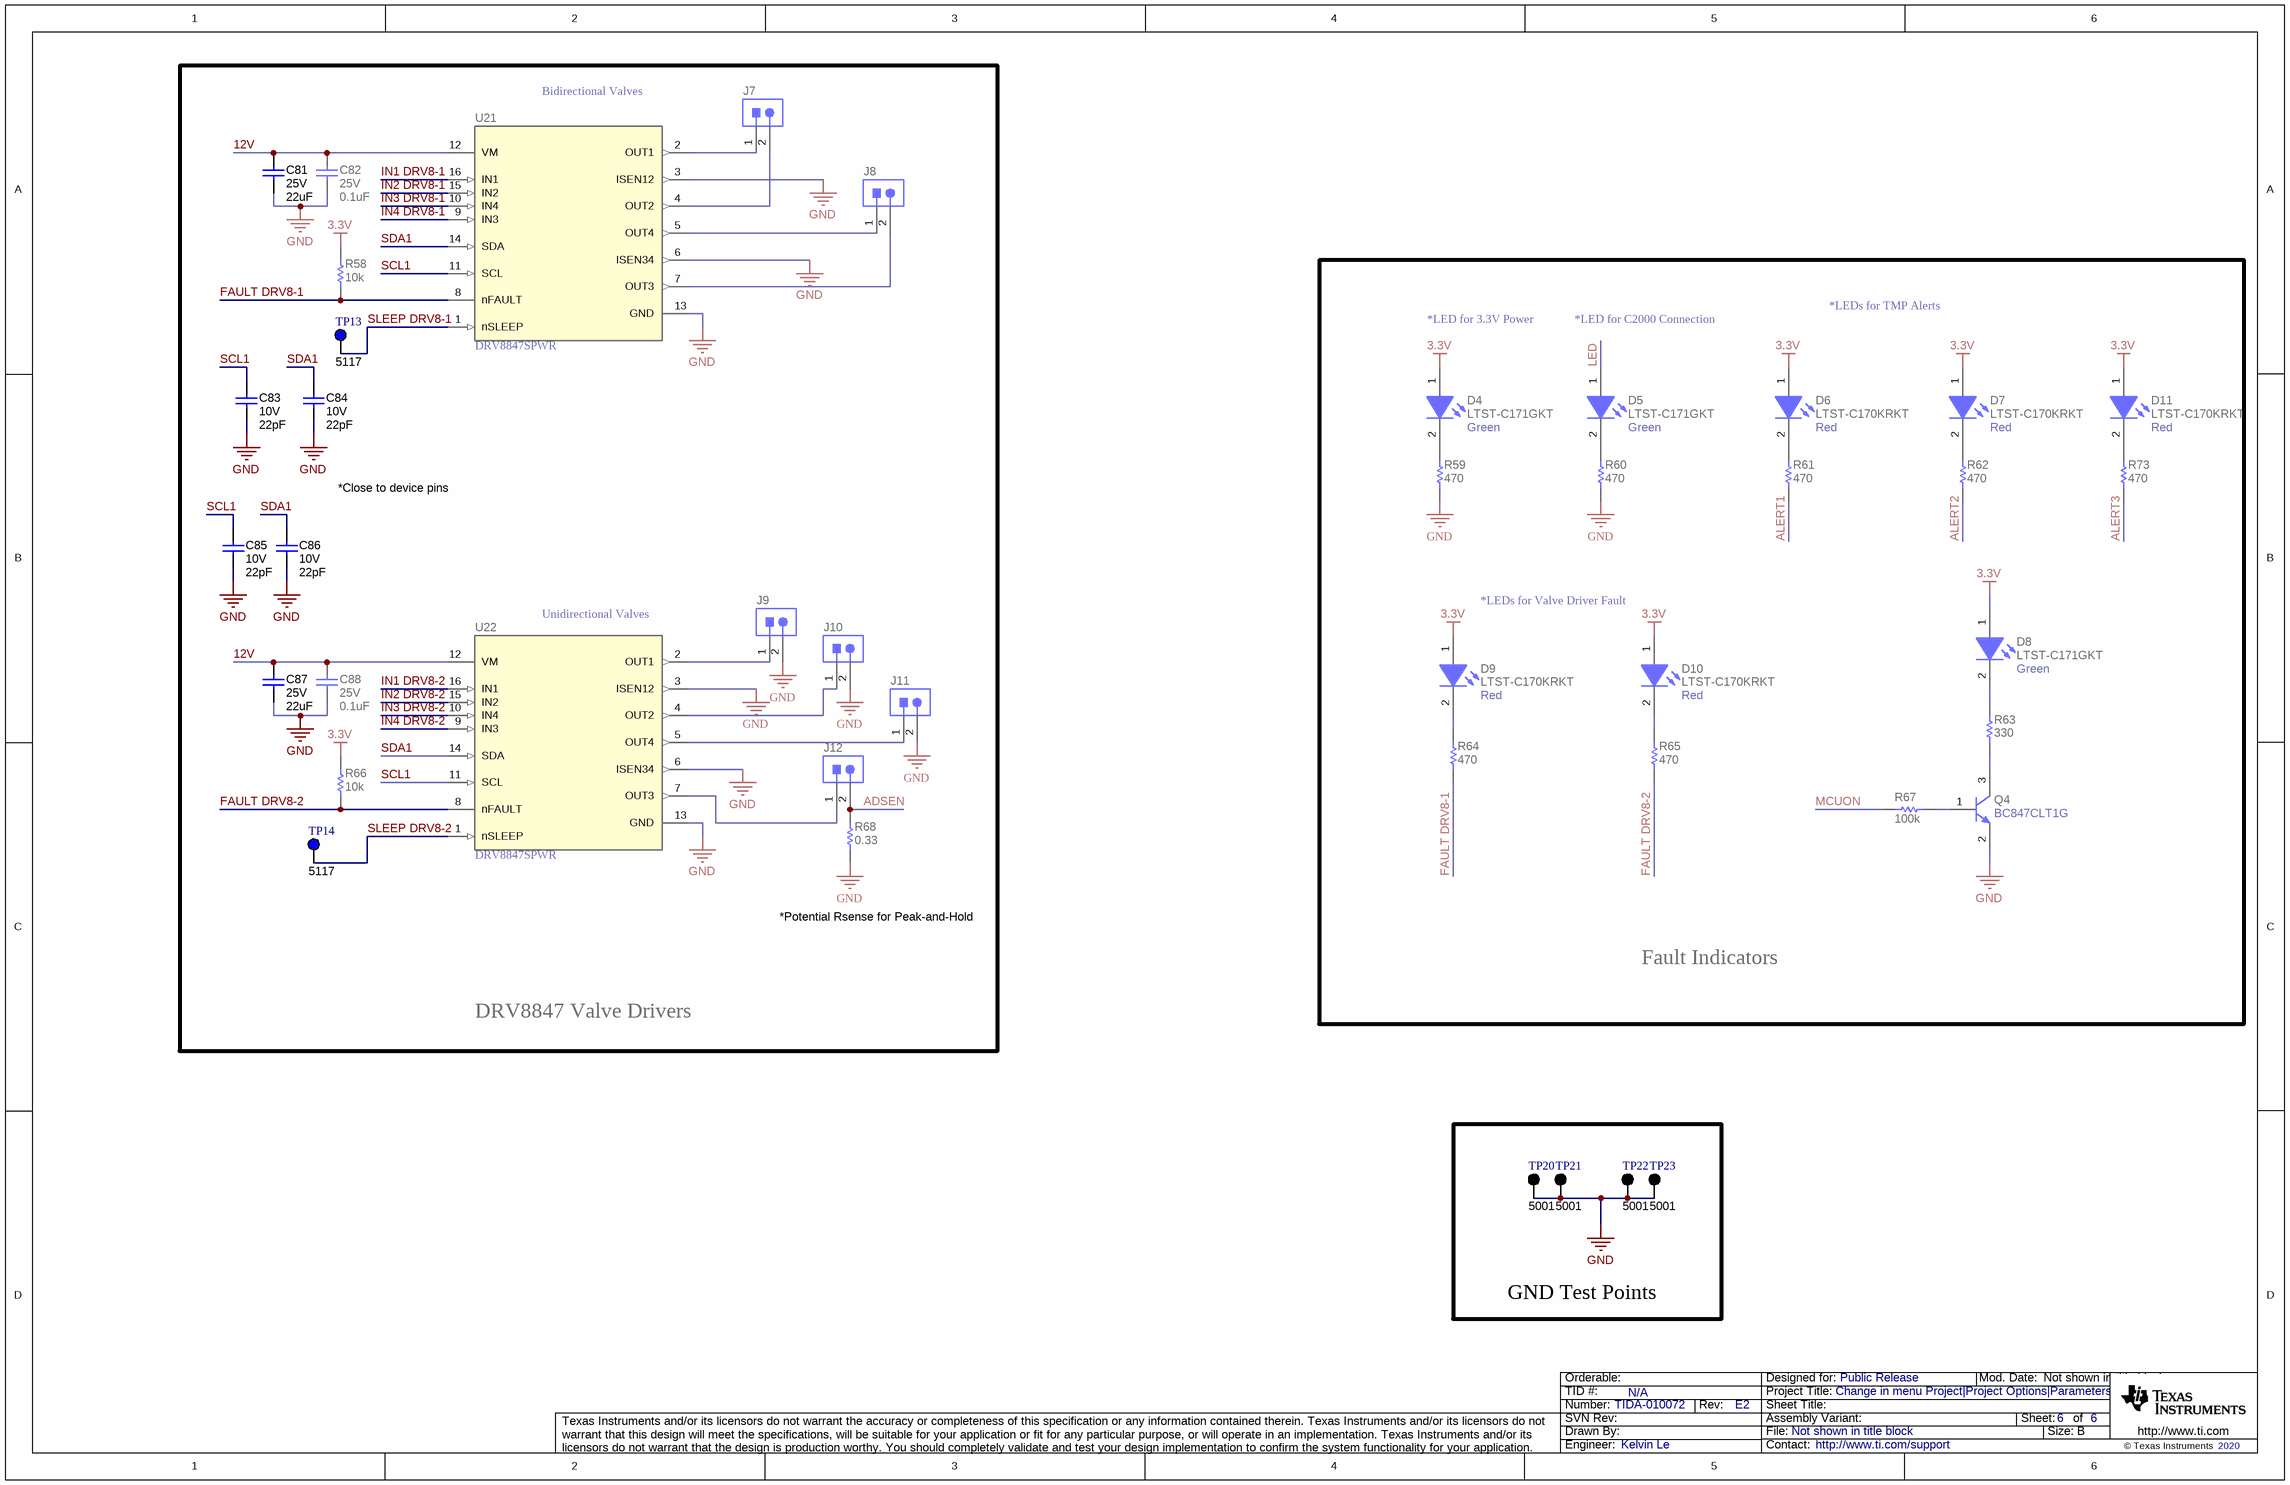
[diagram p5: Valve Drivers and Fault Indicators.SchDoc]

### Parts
C81  VDC_V: 25V  ValueDisplayed: 22uF  [0805_HV]  (hidden comment: GRM21BR61E226ME44L)
C82  VDC_V: 25V  ValueDisplayed: 0.1uF  [0402]  (hidden comment: GRM155R71E104KE14D)
C83  VDC_V: 10V  ValueDisplayed: 22pF  [0402]  (hidden comment: 885012005009)
C84  VDC_V: 10V  ValueDisplayed: 22pF  [0402]  (hidden comment: 885012005009)
C85  VDC_V: 10V  ValueDisplayed: 22pF  [0402]  (hidden comment: 885012005009)
C86  VDC_V: 10V  ValueDisplayed: 22pF  [0402]  (hidden comment: 885012005009)
C87  VDC_V: 25V  ValueDisplayed: 22uF  [0805_HV]  (hidden comment: GRM21BR61E226ME44L)
C88  VDC_V: 25V  ValueDisplayed: 0.1uF  [0402]  (hidden comment: GRM155R71E104KE14D)
D4  LTST-C171GKT  value Green  [LED_LTST-C171]
D5  LTST-C171GKT  value Green  [LED_LTST-C171]
D6  LTST-C170KRKT  value Red  [LED_LTST-C170_Red]
D7  LTST-C170KRKT  value Red  [LED_LTST-C170_Red]
D8  LTST-C171GKT  value Green  [LED_LTST-C171]
D9  LTST-C170KRKT  value Red  [LED_LTST-C170_Red]
D10  LTST-C170KRKT  value Red  [LED_LTST-C170_Red]
D11  LTST-C170KRKT  value Red  [LED_LTST-C170_Red]
J7  61300211121  [WURTH_61300211121]  (value not drawn)
J8  61300211121  [WURTH_61300211121]  (value not drawn)
J9  61300211121  [WURTH_61300211121]  (value not drawn)
J10  61300211121  [WURTH_61300211121]  (value not drawn)
J11  61300211121  [WURTH_61300211121]  (value not drawn)
J12  61300211121  [WURTH_61300211121]  (value not drawn)
Q4  BC847CLT1G  [SOT-23]
R58  ValueDisplayed: 10k  [0402]  (hidden comment: CRCW040210K0JNED)
R59  ValueDisplayed: 470  [0402]  (hidden comment: CRCW0402470RJNED)
R60  ValueDisplayed: 470  [0402]  (hidden comment: CRCW0402470RJNED)
R61  ValueDisplayed: 470  [0402]  (hidden comment: CRCW0402470RJNED)
R62  ValueDisplayed: 470  [0402]  (hidden comment: CRCW0402470RJNED)
R63  ValueDisplayed: 330  [0402]  (hidden comment: CRCW0402330RJNED)
R64  ValueDisplayed: 470  [0402]  (hidden comment: CRCW0402470RJNED)
R65  ValueDisplayed: 470  [0402]  (hidden comment: CRCW0402470RJNED)
R66  ValueDisplayed: 10k  [0402]  (hidden comment: CRCW040210K0JNED)
R67  ValueDisplayed: 100k  [0402]  (hidden comment: CRCW0402100KJNED)
R68  ValueDisplayed: 0.33  [1206]  (hidden comment: CSR1206FKR330)
R73  ValueDisplayed: 470  [0402]  (hidden comment: CRCW0402470RJNED)
TP13  5117  [Keystone5117]
TP14  5117  [Keystone5117]
TP20  5001  [Keystone5001]
TP21  5001  [Keystone5001]
TP22  5001  [Keystone5001]
TP23  5001  [Keystone5001]
U21  DRV8847SPWR  [PW0016A_N]
U22  DRV8847SPWR  [PW0016A_N]

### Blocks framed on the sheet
DRV8847 Valve Drivers: C81-C88 J7-J12 R58 R66 R68 TP13 TP14 U21 U22
Fault Indicators: D4-D11 Q4 R59-R65 R67 R73
GND Test Points: TP20-TP23

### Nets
3.3V: D4.1(A) D6.1(A) D7.1(A) D8.1(A) D9.1(A) D10.1(A) D11.1(A) R58.2 R66.2
GND: C81.2 C82.2 C83.2 C84.2 C85.2 C86.2 C87.2 C88.2 J9.2 J10.2 J11.2 Q4.2(E) R59.1 R60.1 R68.1 TP20.1 TP21.1 TP22.1 TP23.1 U21.3(ISEN12) U21.6(ISEN34) U21.13(GND) U22.3(ISEN12) U22.6(ISEN34) U22.13(GND)
12V: C81.1 C82.1 C87.1 C88.1 U21.12(VM) U22.12(VM)
ADSEN: J12.2 R68.2
ALERT1: R61.1
ALERT2: R62.1
ALERT3: R73.1
FAULT DRV8-1: R58.1 R64.1 U21.8(nFAULT)
FAULT DRV8-2: R65.1 R66.1 U22.8(nFAULT)
IN1 DRV8-1: U21.16(IN1)
IN1 DRV8-2: U22.16(IN1)
IN2 DRV8-1: U21.15(IN2)
IN2 DRV8-2: U22.15(IN2)
IN3 DRV8-1: U21.10(IN4)
IN3 DRV8-2: U22.10(IN4)
IN4 DRV8-1: U21.9(IN3)
IN4 DRV8-2: U22.9(IN3)
LED: D5.1(A)
MCUON: R67.1
SCL1: C83.1 C85.1 U21.11(SCL) U22.11(SCL)
SDA1: C84.1 C86.1 U21.14(SDA) U22.14(SDA)
SLEEP DRV8-1: TP13.1 U21.1(nSLEEP)
SLEEP DRV8-2: TP14.1 U22.1(nSLEEP)
NetD4_2: D4.2(K) R59.2
NetD5_2: D5.2(K) R60.2
NetD6_2: D6.2(K) R61.2
NetD7_2: D7.2(K) R62.2
NetD8_2: D8.2(K) R63.2
NetD9_2: D9.2(K) R64.2
NetD10_2: D10.2(K) R65.2
NetD11_2: D11.2(K) R73.2
NetJ7_1: J7.1 U21.2(OUT1)
NetJ7_2: J7.2 U21.4(OUT2)
NetJ8_1: J8.1 U21.5(OUT4)
NetJ8_2: J8.2 U21.7(OUT3)
NetJ9_1: J9.1 U22.2(OUT1)
NetJ10_1: J10.1 U22.4(OUT2)
NetJ11_1: J11.1 U22.5(OUT4)
NetJ12_1: J12.1 U22.7(OUT3)
NetQ4_1: Q4.1(B) R67.2
NetQ4_3: Q4.3(C) R63.1

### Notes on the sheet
- Bidirectional Valves
- *LED for 3.3V Power
- *LED for C2000 Connection
- *LEDs for TMP Alerts
- *Close to device pins
- (near U22) Unidirectional Valves
- *LEDs for Valve Driver Fault
- *Potential Rsense for Peak-and-Hold

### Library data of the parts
C81 C87 = CMP-0008305-2: CAP, CERM, 22 uF, 25 V, +/- 20%, X5R, 0805; Manufacturer: MuRata; TaMin_C: -55°C; Polarized: N; SizeAreaWB_mm2: 6.75; Value1: Unknown; U/M: EA; Value: 22uF; TaMax_C: 85°C; SizeZ_mm: 1.45; SizeX_mm: 2; SizeY_mm: 1.25; Cap_Case: 0805; SizeArea_mm2: 2.5; Cap_F: 22µF; AEC Category: Q200
C82 C88 = CMP-0006659-2: CAP, CERM, 0.1 uF, 25 V, +/- 10%, X7R, 0402; Manufacturer: MuRata; TaMin_C: -55°C; Polarized: N; SizeAreaWB_mm2: 3; Value1: Unknown; U/M: EA; Value: 0.1uF; TaMax_C: 125°C; SizeZ_mm: 0.6; SizeX_mm: 1; SizeY_mm: 0.5; Cap_F: 100nF; AEC Category: Q200
C83-C86 = CMP-0064912-2: CAP, CERM, 22 pF, 10 V,+/- 5%, C0G/NP0, 0402; Manufacturer: Wurth Elektronik; TaMin_C: -55°C; Polarized: N; SizeAreaWB_mm2: 3; Value1: Unknown; U/M: EA; Value: 22pF; TaMax_C: 125°C; SizeZ_mm: 0.6; SizeX_mm: 1; SizeY_mm: 0.5; AEC Category: Q200
D4 D5 D8 = CMP-0002830-3: LED, Green, SMD; Manufacturer: Lite-On; Io_A: 20A; SizeAreaWB_mm2: 6.75; Value1: W; SizeZ_mm: 1.2; SizeX_mm: 2; SizeY_mm: 1.25; Vf_V: 2.1V; SizeArea_mm2: 2.5; Type: AlInGaP
D6 D7 D9-D11 = CMP-0002829-3: LED, Red, SMD; Manufacturer: Lite-On; Io_A: 20mA; SizeAreaWB_mm2: 6.75; Value1: W; SizeZ_mm: 1.2; SizeX_mm: 2; SizeY_mm: 1.25; Vf_V: 2V; SizeArea_mm2: 2.5; Type: AlInGaP
J7-J12 = CMP-0054794-2: Header, 2.54 mm, 2x1, Gold, TH; Manufacturer: Wurth Elektronik; Shrouded: N; Gender: Male; Green_REACh: Passed; Pitch_mm: 2.54; Green_Lifecycle: Active; Row_Count: 1; Cert_UL: Y
Q4 = CMP-0000376-2: Transistor, NPN, 45 V, 0.1 A, SOT-23; Manufacturer: ON Semiconductor; TaMax_C: 150°C; Value2: 800; Value1: 0.1 A; Vcesat1_V: 700mV; SizeX_mm: 2.5; SizeY_mm: 3; TaMin_C: -55°C; IcRated_A: 100mA; CompType: BJT; SizeZ_mm: 1.1; Value: 45 V; SizeArea_mm2: 7.5; NPN: 1; Vceo_V: 45V; PNP: 0; AEC Category: Q101; SizeAreaWB_mm2: 14; U/M: EA
R58 R66 = CMP-0026825-5: RES, 10 k, 5%, 0.063 W, AEC-Q200 Grade 0, 0402; Manufacturer: Vishay-Dale; Power_W: 63mW; TempCo: 200 ppm/C; Value_Code: 10k0; Value: 10k; EIA_Code: E24; SizeX_mm: 1; SizeY_mm: 0.5; SizeZ_mm: 0.6; Value2: 0.063W; AEC Qualified: Y; VDC_V: 50V; AEC Category: Q200; AEC Grade: 0
R59-R62 R64 R65 R73 = CMP-0026934-3: RES, 470, 5%, 0.063 W, AEC-Q200 Grade 0, 0402; Manufacturer: Vishay-Dale; Power_W: 63mW; TempCo: 200 ppm/C; Value_Code: 470R; Value: 470; EIA_Code: E24; SizeX_mm: 1; SizeY_mm: 0.5; SizeZ_mm: 0.6; Value2: 0.063W; AEC Qualified: Y; VDC_V: 50V; AEC Category: Q200; AEC Grade: 0
R63 = CMP-0026906-3: RES, 330, 5%, 0.063 W, AEC-Q200 Grade 0, 0402; Manufacturer: Vishay-Dale; Power_W: 63mW; TempCo: 200 ppm/C; Value_Code: 330R; Value: 330; EIA_Code: E24; SizeX_mm: 1; SizeY_mm: 0.5; SizeZ_mm: 0.6; Value2: 0.063W; AEC Qualified: Y; VDC_V: 50V; AEC Category: Q200; AEC Grade: 0
R67 = CMP-0026823-3: as R54 on sheet Power Tree
R68 = CMP-0017269-2: RES, 0.33, 1%, 0.5 W, 1206; Manufacturer: Stackpole Electronics Inc; Power_W: 500mW; TempCo: 100 ppm/C; Value_Code: R330; U/M: EA; Value: 0.33; EIA_Code: E96; SizeX_mm: 3.2; SizeY_mm: 1.6; SizeZ_mm: 1.35; Value2: 0.5W; SizeArea_mm2: 5.12; AEC Category: Q200
TP13 TP14 = CMP-0055154-1: Test Point, Miniature, Blue, TH; Manufacturer: Keystone; CNHeader: FALSE; Green_Lifecycle: Active; Green_REACh: Passed; ContactFinish: Silver; CT: TRUE
TP20-TP23 = CMP-0055138-1: Test Point, Miniature, Black, TH; Manufacturer: Keystone; CNHeader: FALSE; Green_Lifecycle: Active; Green_REACh: Passed; ContactFinish: Silver; CT: TRUE
U21 U22 = CMP-0079215-1: Dual H-Bridge Motor Driver, PW0016A (TSSOP-16); Alternate PartNumber: DRV8847SPWT; Alternate Manufacturer: Texas Instruments; SizeAreaWB_mm2: 58.8; SizeZ_mm: 1.2; SizeX_mm: 6.4; SizeY_mm: 5; SizeArea_mm2: 32; CompType: IC; AEC Qualified: N; AEC Category: Q200

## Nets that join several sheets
3.3V: BLDC Motor Driver and TMP Sensors (7 pins), MCU and Connectors (11 pins), Power Tree (5 pins), Valve Drivers and Fault Indicators (9 pins)
4.0V: BLDC Motor Driver and TMP Sensors (5 pins), Power Tree (9 pins)
GND: Hardware (H1.1 H2.1), BLDC Motor Driver and TMP Sensors (58 pins), MCU and Connectors (22 pins), Power Tree (66 pins), Valve Drivers and Fault Indicators (25 pins)
LDO3.3: BLDC Motor Driver and TMP Sensors (13 pins), MCU and Connectors (R32.2 R33.2), Power Tree (C79.1 C80.1 U20.1)
VDRAIN: BLDC Motor Driver and TMP Sensors (18 pins), Power Tree (21 pins)
12V: Power Tree (9 pins), Valve Drivers and Fault Indicators (6 pins)
ADSEN: MCU and Connectors (U8.1), Valve Drivers and Fault Indicators (J12.2 R68.2)
ALERT1: BLDC Motor Driver and TMP Sensors (R6.1 U3.3 U7.10), MCU and Connectors (U8.8), Valve Drivers and Fault Indicators (R61.1)
ALERT2: BLDC Motor Driver and TMP Sensors (R17.1 U5.3 U7.9), MCU and Connectors (U8.7), Valve Drivers and Fault Indicators (R62.1)
ALERT3: BLDC Motor Driver and TMP Sensors (R72.1 U7.12 U24.3), MCU and Connectors (U8.9), Valve Drivers and Fault Indicators (R73.1)
CAL: BLDC Motor Driver and TMP Sensors (U2.34), MCU and Connectors (J2.20 U15.6)
ENABLE: BLDC Motor Driver and TMP Sensors (U7.13), MCU and Connectors (J1.9 U11.3)
FAULT DRV8-1: MCU and Connectors (U8.22), Valve Drivers and Fault Indicators (R58.1 R64.1 U21.8)
FAULT DRV8-2: MCU and Connectors (U8.28), Valve Drivers and Fault Indicators (R65.1 R66.1 U22.8)
IN1 DRV8-1: MCU and Connectors (U8.15), Valve Drivers and Fault Indicators (U21.16)
IN1 DRV8-2: MCU and Connectors (U8.25), Valve Drivers and Fault Indicators (U22.16)
IN2 DRV8-1: MCU and Connectors (U8.16), Valve Drivers and Fault Indicators (U21.15)
IN2 DRV8-2: MCU and Connectors (U8.26), Valve Drivers and Fault Indicators (U22.15)
IN3 DRV8-1: MCU and Connectors (U8.23), Valve Drivers and Fault Indicators (U21.10)
IN3 DRV8-2: MCU and Connectors (U8.33), Valve Drivers and Fault Indicators (U22.10)
IN4 DRV8-1: MCU and Connectors (U8.24), Valve Drivers and Fault Indicators (U21.9)
IN4 DRV8-2: MCU and Connectors (U8.34), Valve Drivers and Fault Indicators (U22.9)
INHA: BLDC Motor Driver and TMP Sensors (U2.37), MCU and Connectors (J2.1 U9.3)
INHB: BLDC Motor Driver and TMP Sensors (U2.39), MCU and Connectors (J2.5 U9.4)
INHC: BLDC Motor Driver and TMP Sensors (U2.41), MCU and Connectors (J2.9 U14.6)
INLA: BLDC Motor Driver and TMP Sensors (U2.38), MCU and Connectors (J2.3 U9.1)
INLB: BLDC Motor Driver and TMP Sensors (U2.40), MCU and Connectors (J2.7 U9.6)
INLC: BLDC Motor Driver and TMP Sensors (U2.42), MCU and Connectors (J2.11 U14.4)
ISENA: BLDC Motor Driver and TMP Sensors (C32.1 R27.2), MCU and Connectors (J1.16 U11.4)
ISENB: BLDC Motor Driver and TMP Sensors (C33.1 R28.2), MCU and Connectors (J1.14 U11.6)
ISENC: BLDC Motor Driver and TMP Sensors (C31.1 R26.2), MCU and Connectors (J1.12 U11.1)
LED: MCU and Connectors (J2.15 U14.3), Valve Drivers and Fault Indicators (D5.1)
MCUON: MCU and Connectors (U8.10), Valve Drivers and Fault Indicators (R67.1)
MOTA: BLDC Motor Driver and TMP Sensors (11 pins), MCU and Connectors (J5.1)
MOTB: BLDC Motor Driver and TMP Sensors (11 pins), MCU and Connectors (J5.2)
MOTC: BLDC Motor Driver and TMP Sensors (11 pins), MCU and Connectors (J5.3)
nFAULT: BLDC Motor Driver and TMP Sensors (R18.1 R19.1 U2.28), MCU and Connectors (J1.15 U10.6)
SCL1: MCU and Connectors (C39.1 J17.2 R33.1 U8.11), Valve Drivers and Fault Indicators (C83.1 C85.1 U21.11 U22.11)
SCL2: BLDC Motor Driver and TMP Sensors (6 pins), MCU and Connectors (C36.1 J18.2 R30.1 U8.39)
SCLK: BLDC Motor Driver and TMP Sensors (U2.31), MCU and Connectors (J1.13 U10.1)
SCS: BLDC Motor Driver and TMP Sensors (U2.32), MCU and Connectors (J2.18 U15.4)
SD_N: BLDC Motor Driver and TMP Sensors (R10.1 U2.29), MCU and Connectors (J2.14 U15.3)
SD_P: BLDC Motor Driver and TMP Sensors (U2.30), MCU and Connectors (J2.12 U15.1)
SDA1: MCU and Connectors (C38.1 J17.1 R32.1 U8.12), Valve Drivers and Fault Indicators (C84.1 C86.1 U21.14 U22.14)
SDA2: BLDC Motor Driver and TMP Sensors (6 pins), MCU and Connectors (C37.1 J18.1 R31.1 U8.40)
SLEEP DRV8-1: MCU and Connectors (U8.21), Valve Drivers and Fault Indicators (TP13.1 U21.1)
SLEEP DRV8-2: MCU and Connectors (U8.27), Valve Drivers and Fault Indicators (TP14.1 U22.1)
VSENA: BLDC Motor Driver and TMP Sensors (C8.1 R2.1 R4.2), MCU and Connectors (J1.6 U12.3)
VSENB: BLDC Motor Driver and TMP Sensors (C17.1 R11.1 R14.2), MCU and Connectors (J1.8 U12.6)
VSENC: BLDC Motor Driver and TMP Sensors (C29.1 R23.1 R24.2), MCU and Connectors (J1.10 U12.4)
VSENVM: BLDC Motor Driver and TMP Sensors (C6.1 R1.1 R3.2), MCU and Connectors (J1.3 U12.1)

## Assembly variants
001: not fitted C41 C53 C57 C70 C74 C77 C80 C93 R38 R39 R41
